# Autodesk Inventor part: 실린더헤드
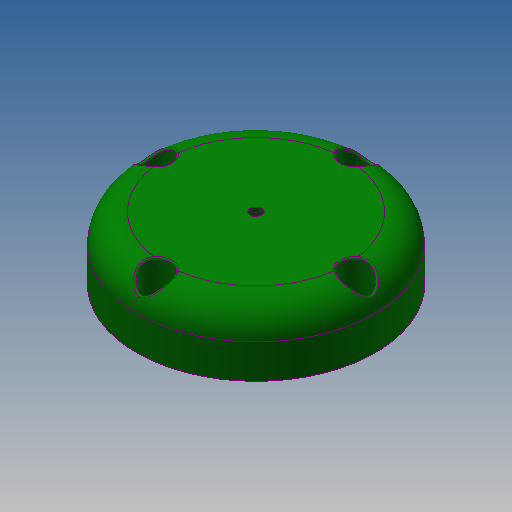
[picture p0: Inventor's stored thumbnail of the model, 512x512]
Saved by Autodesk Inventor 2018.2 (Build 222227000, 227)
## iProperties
Created: 2016-11
Part Number: 실린더헤드
Material: 알루미늄 6061
Document SubType Name: Modeling
Designer: mduedu
Density: 2.71 g/cm^3
Mass: 235.592 g
Surface Area: 209.258 cm^2
Volume: 86.9344 cm^3
Appearance: 진녹색
Author: mduedu
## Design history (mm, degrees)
sketch "스케치1"
  geometry: C1 r 42 at (0, 0); 1 further point
  constraints: 1 centre point, 1 coincident
  dimensions: "d0" = 84 diameter of C1
extrude "돌출1" new body sketch "스케치1" distance "d1" = 22; taper "d2" = 0 deg
fillet "모깎기1" dims "d3" = 10
sketch "스케치2"
  geometry: C1 r 30 at (0, 0); 1 further point
  constraints: 1 centre point, 1 coincident
  dimensions: "d4" = 60 diameter of C1
extrude "돌출2" join sketch "스케치2" distance "d5" = 5; taper "d6" = 0 deg
sketch "스케치3"
  geometry: C1 r 25 at (0, 0); 1 further point
  constraints: 1 centre point, 1 coincident
  dimensions: "d7" = 50 diameter of C1
extrude "돌출3" cut sketch "스케치3" distance "d8" = 18; taper "d9" = 0 deg
hole "구멍1" diameter "d12" = 4.134; stored, may be unused: countersink angle "d16" = 90 deg, drill point angle "d18" = 118 deg; dims "d10" = 10, "d11" = 10, "d13" = 6, "d14" = 4, "d15" = 2, "d17" = 8
chamfer "모따기1" distance "d19" = 1; stored, may be unused: second distance "d20" = 2, angle "d21" = 45 deg
fillet "모깎기2" dims "d22" = 3
sketch "스케치4"
  geometry: C1 r 17.5 at (0, 0); 1 further point
  constraints: 1 centre point, 1 coincident
  dimensions: "d23" = 35 diameter of C1
extrude "돌출4" cut sketch "스케치4" distance "d24" = 3; taper "d25" = 0 deg
fillet "모깎기3" dims "d26" = 0.5
sketch "스케치5" dims "d32" = 70
  geometry: C1 r 5 at (0, 35); 3 further points
  constraints: 2 coincident, 2 vertical alignment, 1 centre point, 2 other
  dimensions: "d33" = 10 diameter of C1
extrude "돌출5" cut sketch "스케치5" distance "d34" = 12; taper "d35" = 0 deg
sketch "스케치6" dims "d39" = 70
  geometry: 6 further points
  constraints: 2 vertical alignment, 1 coincident, 7 other
  dimensions: "d42" = 360 deg dimension on point (0, -35) point (0, 0) (derived)
sketch "스케치7"
  geometry: 4 further points
  constraints: 4 other
hole "구멍2" sketch "스케치7" at (0, 70), (-35, 35), (35, 35), (0, 0) diameter "d44" = 5.5; stored, may be unused: countersink angle "d48" = 90 deg, drill point angle "d50" = 0 deg; dims "d45" = 6, "d46" = 4, "d47" = 2, "d49" = 8
fillet "모깎기4" dims "d51" = 0.5
chamfer "모따기2" distance "d54" = 5; stored, may be unused: second distance "d55" = 2, angle "d56" = 30 deg
node "솔리드1"
pattern_circular "원형 패턴1" dims angle "d37" = 360 deg
